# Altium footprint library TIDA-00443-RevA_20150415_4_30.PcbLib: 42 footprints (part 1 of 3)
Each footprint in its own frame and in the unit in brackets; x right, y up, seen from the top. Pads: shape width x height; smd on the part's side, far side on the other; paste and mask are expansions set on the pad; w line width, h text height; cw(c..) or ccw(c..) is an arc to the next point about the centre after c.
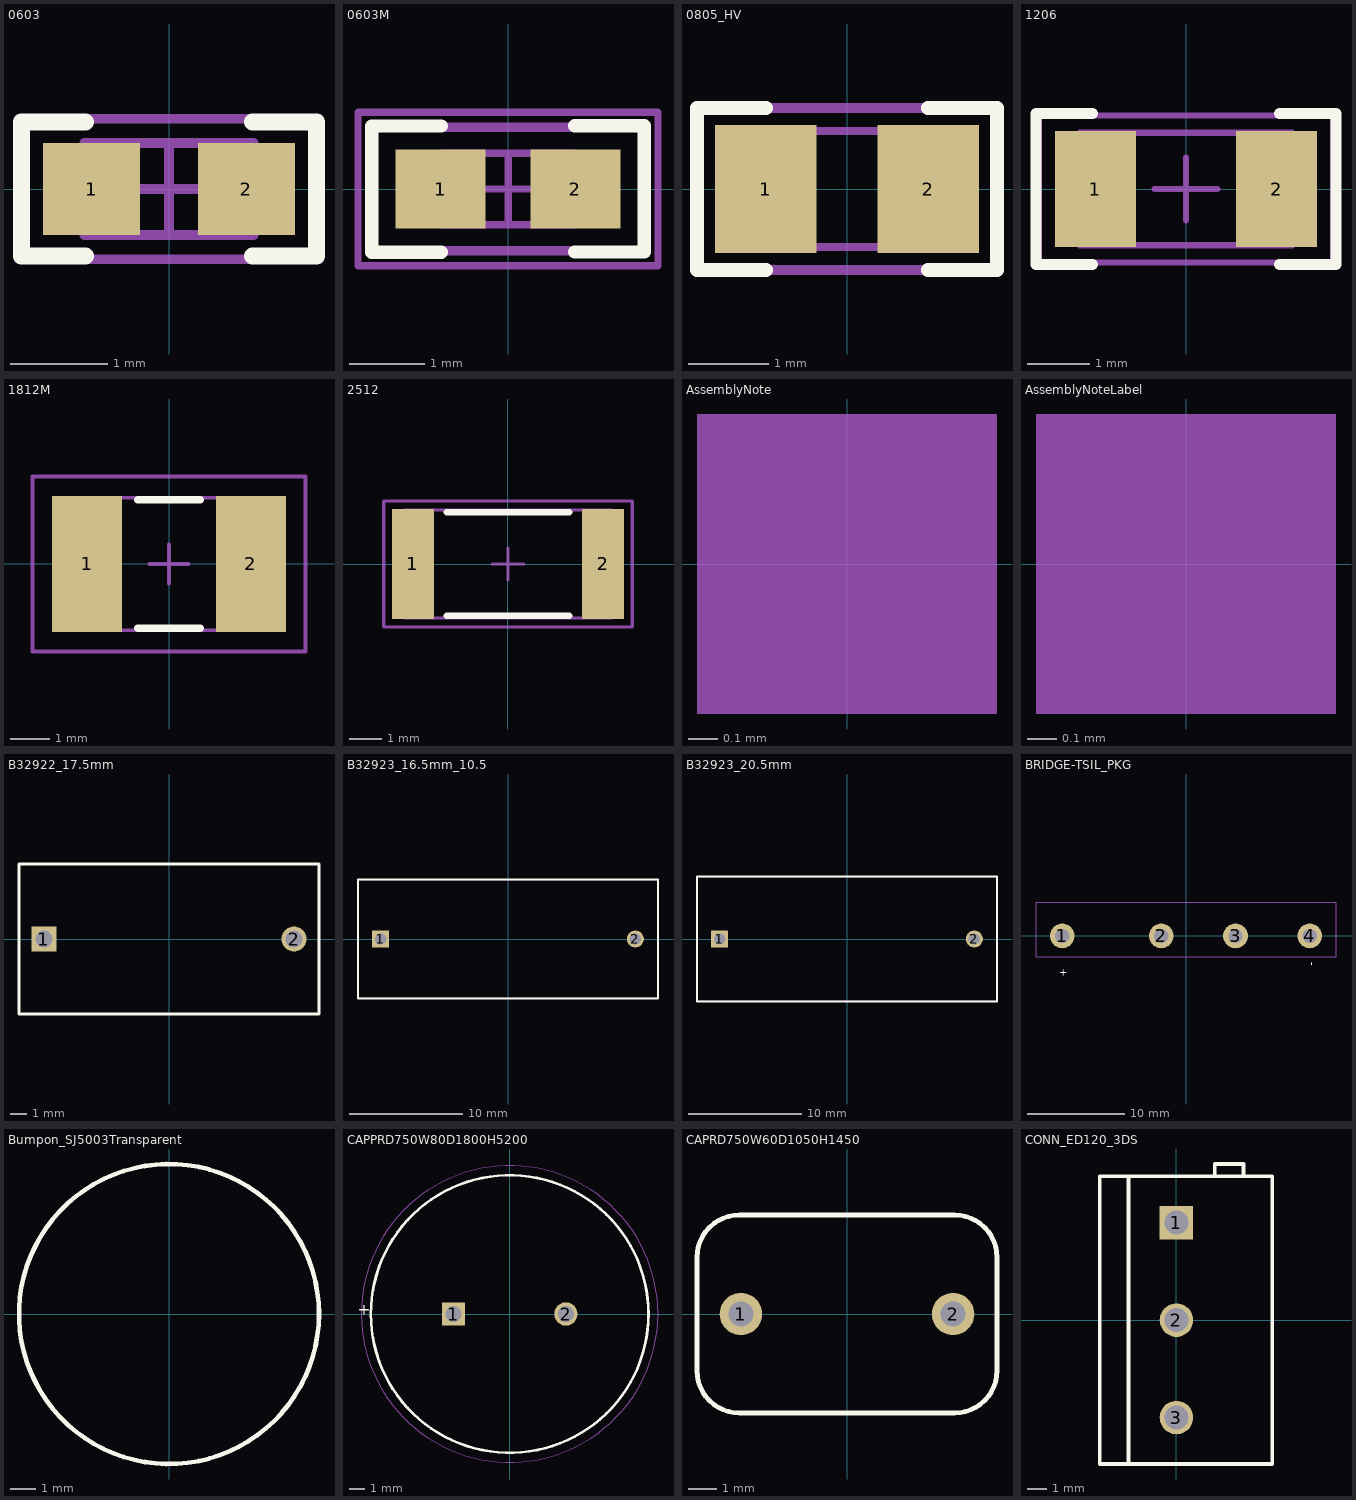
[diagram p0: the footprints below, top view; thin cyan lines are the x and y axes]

## 0603 [mm] "0603 from SM-752 data"
height 0.85
pads (2):
  rect 1x0.95 smd: 1(-0.8,0) 2(0.8,0)
Top Overlay:
  lines w0.178: -0.864,-0.691 -1.524,-0.691 -1.524,0.693 -0.864,0.693 ; 0.864,-0.691 1.524,-0.691 1.524,0.693 0.864,0.693
Mechanical 5:
  lines w0.1: -1.55,-0.725 -1.55,0.725 1.55,0.725 1.55,-0.725 -1.55,-0.725
  text ".Designator" at -0.864,-0.356 h0.76
Mechanical 13:
  lines w0.1: -0.55,-0.475 -0.55,0.475 ; 0.55,-0.475 0.55,0.475 ; -0.875,-0.475 0.875,-0.475 0.875,0.475 -0.875,0.475 -0.875,-0.475
Mechanical 15:
  lines w0.1: -0.475,0 0.475,0 ; 0,-0.475 0,0.475 ; -1.55,-0.725 1.55,-0.725 1.55,0.725 -1.55,0.725 -1.55,-0.725
3D body: height 0.85, standoff 0, extent -0.874,-0.474 -0.551,0.474
3D body: height 0.85, standoff 0, extent -0.549,-0.474 0.549,0.474
3D body: height 0.85, standoff 0, extent 0.551,-0.474 0.874,0.474

## 0603M [mm] "0603 from SM-752 data"
height 0.85
pads (2):
  rect 1.2x1.05 smd: 1(-0.9,0) 2(0.9,0)
Top Overlay:
  lines w0.178: -1.819,0.805 -1.819,-0.843 -0.889,-0.843 ; -1.819,0.841 -0.889,0.841 ; 0.889,-0.841 1.819,-0.841 ; 0.889,0.843 1.819,0.843 1.819,-0.805
Mechanical 5:
  lines w0.127: -1.825,-0.825 -1.825,0.825 1.825,0.825 1.825,-0.825 -1.825,-0.825
  text ".Designator" at 0.686,0.356 h0.76
Mechanical 13:
  lines w0.1: -0.55,-0.475 -0.55,0.475 ; 0.55,-0.475 0.55,0.475 ; -0.875,-0.475 -0.875,0.475 0.875,0.475 0.875,-0.475 -0.875,-0.475
Mechanical 15:
  lines w0.1: -0.475,0 0.475,0 ; 0,-0.475 0,0.475 ; -2,-1.025 -2,1.025 2,1.025 2,-1.025 -2,-1.025
3D body: height 0.85, standoff 0, extent 0.551,-0.474 0.874,0.474
3D body: height 0.85, standoff 0, extent -0.549,-0.474 0.549,0.474
3D body: height 0.85, standoff 0, extent -0.874,-0.474 -0.551,0.474

## 0805_HV [mil] "0805 with 30mil clearance between pads"
height 43.31
pads (2):
  rect 50x63 smd: 1(-40,0) 2(40,0)
Top Overlay:
  lines w7: -40,-40 -74,-40 -74,0 -74,40 -40,40 ; 40,-40 74,-40 74,0 74,40 40,40
Mechanical 5:
  lines w5: -74,-40 74,-40 74,40 -74,40 -74,-40
  text ".Designator" at 38,19 h35
Mechanical 13:
  lines w3.94: -25.59,-28.54 -25.59,28.54 ; 25.59,-28.54 25.59,28.54 ; -43.31,-28.54 -43.31,28.54 43.31,28.54 43.31,-28.54 -43.31,-28.54
3D body: height 43.31, standoff 0, extent 25.61,-28.52 43.29,28.52
3D body: height 43.31, standoff 0, extent -25.57,-28.52 25.57,28.52
3D body: height 43.31, standoff 0, extent -43.29,-28.52 -25.61,28.52

## 1206 [mm] "1206 from SM-752 data"
height 1.35
pads (2):
  rect 1.3x1.85 smd: 1(-1.45,0) 2(1.45,0)
Top Overlay:
  lines w0.178: -1.5,-1.21 -2.4,-1.21 -2.4,1.21 -1.5,1.21 ; 1.5,-1.21 2.4,-1.21 2.4,1.21 1.5,1.21
Mechanical 5:
  lines w0.1: -1.7,-0.9 -1.7,0.9 1.7,0.9 1.7,-0.9 -1.7,-0.9
  text ".Designator" at -0.508,-0.305 h0.76
Mechanical 13:
  lines w0.1: -1.2,-0.9 -1.2,0.9 ; 1.2,-0.9 1.2,0.9 ; -1.7,-0.9 -1.7,0.9 1.7,0.9 1.7,-0.9 -1.7,-0.9
Mechanical 15:
  lines w0.1: -0.5,0 0.5,0 ; 0,-0.5 0,0.5 ; -2.35,-1.175 -2.35,1.175 2.35,1.175 2.35,-1.175 -2.35,-1.175
3D body: height 1.35, standoff 0, extent 1.201,-0.899 1.699,0.899
3D body: height 1.35, standoff 0, extent -1.199,-0.899 1.199,0.899
3D body: height 1.35, standoff 0, extent -1.699,-0.899 -1.201,0.899

## 1812M [mm]
height 1.35
pads (2):
  rect 1.8x3.5 smd: 1(-2.1,0) 2(2.1,0)
Top Overlay:
  lines w0.2: -0.8,-1.65 0.8,-1.65 ; -0.8,1.65 0.8,1.65
Mechanical 5:
  lines w0.1: -2.4,-1.7 -2.4,1.7 2.4,1.7 2.4,-1.7 -2.4,-1.7
  text ".Designator" at 1.143,0.432 h0.76
Mechanical 13:
  lines w0.1: -1.9,-1.7 -1.9,1.7 ; 1.9,-1.7 1.9,1.7 ; -2.4,-1.7 2.4,-1.7 2.4,1.7 -2.4,1.7 -2.4,-1.7
Mechanical 15:
  lines w0.1: -0.5,0 0.5,0 ; 0,-0.5 0,0.5 ; -3.5,-2.25 3.5,-2.25 3.5,2.25 -3.5,2.25 -3.5,-2.25
3D body: height 1.35, standoff 0, extent 1.901,-1.699 2.399,1.699
3D body: height 1.35, standoff 0, extent -1.899,-1.699 1.899,1.699
3D body: height 1.35, standoff 0, extent -2.399,-1.699 -1.901,1.699

## 2512 [mm] "Chip Resistor, Body 6.3x3.2mm, IPC Medium Density"
height 0.71
pads (2):
  rect 1.3x3.4 smd: 1(-2.95,0) 2(2.95,0)
Top Overlay:
  lines w0.2: -1.9,-1.6 1.9,-1.6 ; -1.9,1.6 1.9,1.6
Mechanical 5:
  lines w0.1: -3.225,-1.675 3.225,-1.675 3.225,1.675 -3.225,1.675 -3.225,-1.675
  text ".Designator" at -0.051,-0.813 h0.76
Mechanical 13:
  lines w0.1: -2.463,-1.675 -2.463,1.675 ; 2.463,-1.675 2.463,1.675 ; -3.225,-1.675 3.225,-1.675 3.225,1.675 -3.225,1.675 -3.225,-1.675
Mechanical 15:
  lines w0.1: -0.5,0 0.5,0 ; 0,-0.5 0,0.5 ; -3.85,-1.95 3.85,-1.95 3.85,1.95 -3.85,1.95 -3.85,-1.95
3D body: height 0.71, standoff 0, extent -3.224,-1.674 -2.464,1.674
3D body: height 0.71, standoff 0, extent -2.462,-1.674 2.462,1.674
3D body: height 0.71, standoff 0, extent 2.464,-1.674 3.224,1.674

## AssemblyNote [mm] "Assembly Note"
Mechanical 5:
  rectangle: -0.508,-0.508 0.508,0.508
  text ".Designator" at -4.191,-0.508 h0.76
  text ".Comment" at 1.143,-0.508 h0.76

## AssemblyNoteLabel [mm] "Assembly Note for PCB Labels"
Mechanical 5:
  rectangle: -0.508,-0.508 0.508,0.508
  text "Install label in silkscreened box after final wash.  Text shall be 8 pt font.  Text shall be per the Label Table in the PDF schematic." at 1.143,-0.508 h0.76
  text ".Designator" at -4.191,-0.508 h0.76

## B32922_17.5mm [mm] "Epcos film capacitors, 15mm spacing"
height 17.5
pads (2):
  rect 1.5x1.5 hole 1: 1(-7.5,0)
  round 1.5 hole 1: 2(7.5,0)
Top Overlay:
  lines w0.178: -9,-4.5 0,-4.5 9,-4.5 9,0 9,4.5 0,4.5 -9,4.5 -9,0 -9,-4.5
Mechanical 5:
  lines w0.127: -9,-4.5 -9,0 -9,4.5 0,4.5 9,4.5 9,0 9,-4.5 0,-4.5 -9,-4.5
  text ".Designator" at 0.457,0 h0.76
3D body: height 17.5, standoff 0, extent -8.999,-4.499 8.999,4.499

## B32923_16.5mm_10.5 [mm] "Epcos film capacitors, 22.5mm spacing"
height 16.5
pads (2):
  rect 1.5x1.5 hole 1: 1(-11.25,0)
  round 1.5 hole 1: 2(11.25,0)
Top Overlay:
  lines w0.178: -13.25,-5.25 -13.25,0 -13.25,5.25 0,5.25 13.25,5.25 13.25,0 13.25,-5.25 0,-5.25 -13.25,-5.25
Mechanical 5:
  lines w0.127: -13.25,-5.25 0,-5.25 13.25,-5.25 13.25,0 13.25,5.25 0,5.25 -13.25,5.25 -13.25,0 -13.25,-5.25
  text ".Designator" at -2.794,0.356 h0.76
3D body: height 16.5, standoff 0, extent -13.249,-5.249 13.249,5.249

## B32923_20.5mm [mm] "Epcos film capacitors, 22.5mm spacing"
height 20.5
pads (2):
  rect 1.5x1.5 hole 1: 1(-11.25,0)
  round 1.5 hole 1: 2(11.25,0)
Top Overlay:
  lines w0.178: -13.25,-5.5 0,-5.5 13.25,-5.5 13.25,0 13.25,5.5 0,5.5 -13.25,5.5 -13.25,0 -13.25,-5.5
Mechanical 5:
  lines w0.127: -13.25,-5.5 -13.25,0 -13.25,5.5 0,5.5 13.25,5.5 13.25,0 13.25,-5.5 0,-5.5 -13.25,-5.5
  text ".Designator" at -1.524,-0.508 h1.02
3D body: height 20.5, standoff 0, extent -13.249,-5.499 13.249,5.499

## BRIDGE-TSIL_PKG [mil]
pads (4):
  round 100 hole 57: 1(-500,0) 2(-100,0) 3(200,0) 4(500,0)
Top Overlay:
  text "+" at -512,-161 h30
  text "-" at 520,-120 h30
Mechanical 5:
  lines w5: -606,-84 -606,136 606,136 606,-84 -606,-84
  text ".Designator" at 37,-13 h30
  text "-" at 579,-124 h30
  text "+" at -578,-132 h30

## Bumpon_SJ5003Transparent [mil] "3M Hemispherical Bumpon transparent"
height 200
pads (1):
  round 1 on Mech3: 0(0,0)
Top Overlay:
  circle w7: c0,0 r228.04
Mechanical 5:
  circle w5: c0,0 r228.04
  text ".Designator" at -60,-20 h30
3D body: height 196.82, standoff 0, extent -216.78,-218.07 218.51,218.08

## CAPPRD750W80D1800H5200 [mm] "Capacitor, Aluminum Electrolytic, Radial; Body 18 x 50 mm (Dia.xH typ); Pin Spacing 7.5 mm (typ)"
height 52
pads (2):
  rect 1.554x1.554 hole 1.054: 1(-3.75,0)
  round 1.554 hole 1.054: 2(3.75,0)
Top Overlay:
  circle w0.178: c0,0 r9.25
  text "+" at -10.109,-0.051 h0.76
Mechanical 5:
  circle w0.127: c0,0 r9.25
  text "+" at -10.058,-0.406 h0.76
  text ".Designator" at 0.178,-0.584 h0.76
Mechanical 15:
  circle w0.05: c0,0 r9.885
Mechanical 17:
  text "LEAD LENGTH: 15 MIN" at -13.335,11.43 h1.52
3D body: height 52, standoff 0, extent -9.177,-9.232 9.25,9.232

## CAPRD750W60D1050H1450 [mm] "TDK"
height 14.5
pads (2):
  round 1.5 hole 0.889: 1(-3.75,0) 2(3.75,0)
Top Overlay:
  lines w0.17: -5.3,-2 ccw(c-3.8,-2) -3.8,-3.5 3.8,-3.5 ccw(c3.8,-2) 5.3,-2 5.3,2 ccw(c3.8,2) 3.8,3.5 -3.8,3.5 ccw(c-3.8,2) -5.3,2 -5.3,-2
Mechanical 5:
  lines w0.1: -5.3,-2 ccw(c-3.8,-2) -3.8,-3.5 3.8,-3.5 ccw(c3.8,-2) 5.3,-2 5.3,2 ccw(c3.8,2) 3.8,3.5 -3.8,3.5 ccw(c-3.8,2) -5.3,2 -5.3,-2
  text ".Designator" at -0.483,0.711 h0.76
3D body: height 7.5, standoff -1.5, extent -4.048,-0.299 -3.45,0.3
3D body: height 7.5, standoff -1.5, extent 3.452,-0.299 4.05,0.3
3D body: height 14.46, standoff 4, extent -5.24,-3.5 5.24,3.5

## CONN_ED120_3DS [mm] "ONSHORE"
height 13
pads (3):
  rect 1.75x1.75 hole 1.25: 1(0,5.08)
  round 1.75 hole 1.25: 2(0,0) 3(0,-5.08)
Top Overlay:
  lines w0.2: -2.5,-7.5 -2.5,7.5 ; 2,7.5 2,8.14 3.5,8.14 3.5,7.5 ; -4,-7.5 -4,7.5 5,7.5 5,-7.5 -4,-7.5
Mechanical 5:
  lines w0.1: -2.5,-7.5 -2.5,7.5 ; 2,7.5 2,8.14 3.5,8.14 3.5,7.5 ; -4,-7.5 5,-7.5 5,7.5 -4,7.5 -4,-7.5
  text ".Designator" at 1.448,0.94 h0.76
3D body: height 13, standoff 0, extent -4.05,-7.55 5.05,7.55
3D body: height 12.9, standoff -2.5, extent -0.5,-5.459 0.496,-4.461
3D body: height 6, standoff 4, extent -4.125,-6.067 0.875,-4.075
3D body: height 13.1, standoff 12.5, extent -1,-6.071 0.992,-4.075
3D body: height 13, standoff 0, extent 2,7.54 3.5,8.14
3D body: height 6, standoff 4, extent -4.1,4.046 0.9,6.038
3D body: height 13.1, standoff 12.5, extent -1,4.082 0.992,6.078
3D body: height 13.1, standoff 12.5, extent -1,-0.998 0.992,0.998
3D body: height 6, standoff 4, extent -4.1,-1.054 0.9,0.938
3D body: height 12.9, standoff -2.5, extent -0.5,-0.499 0.496,0.499
3D body: height 12.9, standoff -2.5, extent -0.5,4.581 0.496,5.579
